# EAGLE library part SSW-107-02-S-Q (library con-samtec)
THROUGH-HOLE .025" SQ POST SOCKET Source: Samtec SSW.pdf
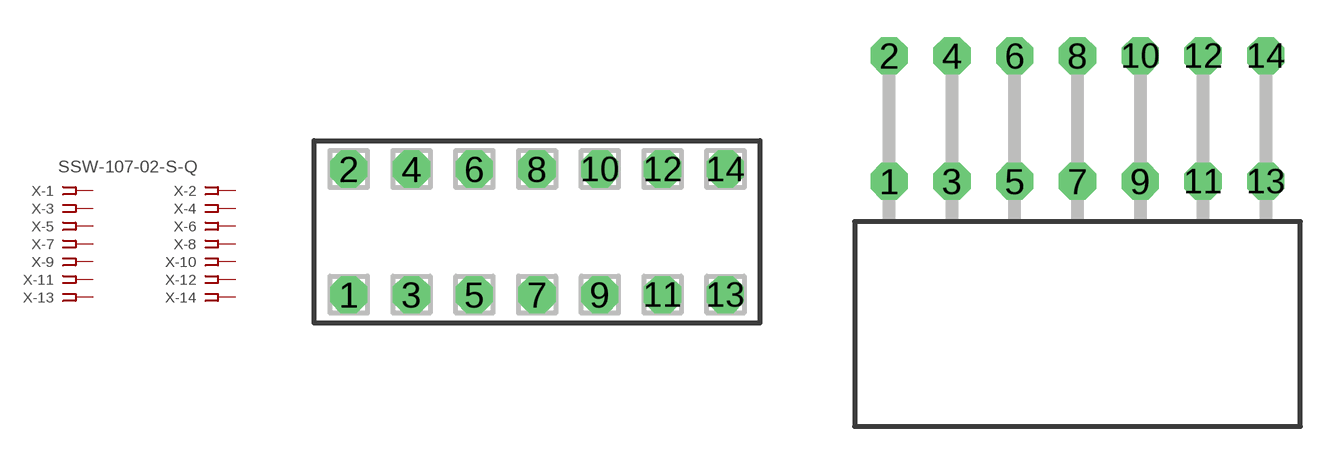
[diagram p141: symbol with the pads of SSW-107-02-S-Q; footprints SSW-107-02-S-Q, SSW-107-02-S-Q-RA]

Designator prefix X; gates -1=FPINV -2=FPIN -3=FPIN -4=FPIN -5=FPIN -6=FPIN -7=FPIN -8=FPIN -9=FPIN -10=FPIN -11=FPIN -12=FPIN -13=FPIN -14=FPIN

## SSW-107-02-S-Q (MPN: SSW-107-02-S-Q; OC_FARNELL: unknown; OC_NEWARK: 82P3882)  [SSW-107-02-S-Q]
1  -1:1  pas
2  -2:1  pas
3  -3:1  pas
4  -4:1  pas
5  -5:1  pas
6  -6:1  pas
7  -7:1  pas
8  -8:1  pas
9  -9:1  pas
10  -10:1  pas
11  -11:1  pas
12  -12:1  pas
13  -13:1  pas
14  -14:1  pas

## SSW-107-02-S-QRA (MPN: SSW-107-02-S-Q-RA; OC_FARNELL: unknown; OC_NEWARK: 82P3883)  [SSW-107-02-S-Q-RA]
Pads as for SSW-107-02-S-Q

## Footprint SSW-107-02-S-Q (pad centres in mm)
THROUGH-HOLE .025" SQ POST SOCKET Source: Samtec SSW.pdf
drill 1 pad 1.5 octagon: 1 -7.62,-2.54; 2 -7.62,2.54; 3 -5.08,-2.54; 4 -5.08,2.54; 5 -2.54,-2.54; 6 -2.54,2.54; 7 0,-2.54; 8 0,2.54; 9 2.54,-2.54; 10 2.54,2.54; 11 5.08,-2.54; 12 5.08,2.54; 13 7.62,-2.54; 14 7.62,2.54

## Footprint SSW-107-02-S-Q-RA (pad centres in mm)
THROUGH-HOLE .025" SQ POST SOCKET Source: Samtec SSW.pdf
drill 1 pad 1.5 octagon: 1 -7.62,1.524; 2 -7.62,6.604; 3 -5.08,1.524; 4 -5.08,6.604; 5 -2.54,1.524; 6 -2.54,6.604; 7 0,1.524; 8 0,6.604; 9 2.54,1.524; 10 2.54,6.604; 11 5.08,1.524; 12 5.08,6.604; 13 7.62,1.524; 14 7.62,6.604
